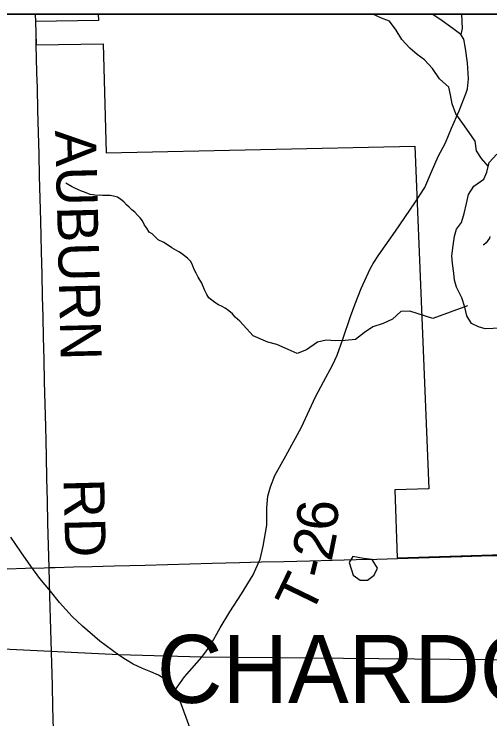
# Model space of a CAD drawing. Extents: x -6.1 to 38, y -7.7 to 22.
# Drawn here: x 4.259 to 4.922, y 19.918 to 20.9 of the extents above; entities that cross this region are included whole.
import ezdxf

# ---------------------------------------------------------------- set-up
doc = ezdxf.new("R2010")
doc.units = 0
for name, color, linetype in [('GM_X_Corporation', 7, 'Continuous'), ('GM_X_Corporation_Text', 7, 'Continuous'), ('GM_X_County_Road', 7, 'Continuous'), ('GM_X_County_Road_Text', 7, 'Continuous'), ('GM_X_Minor_Lake', 7, 'Continuous'), ('GM_X_Minor_River', 7, 'Continuous'), ('GM_X_Township_Road', 7, 'Continuous'), ('GM_X_Township_Road_Text', 7, 'Continuous'), ('GM_X_US_Route', 7, 'Continuous'), ('SH_Data', 7, 'Continuous')]:
    doc.layers.add(name, color=color, linetype=linetype)

msp = doc.modelspace()

# ---------------------------------------------------------------- linework, layer by layer
at = {"layer": 'GM_X_Corporation'}
for points in [[(4.22089, 19.39843), (4.27649, 19.3997), (4.32704, 19.40086), (4.34441, 19.40116), (4.39909, 19.40211), (4.59553, 19.40667), (4.87412, 19.41274), (4.97606, 19.41491), (5.07728, 19.4172), (5.13005, 19.41862), (5.18283, 19.42005), (5.26822, 19.42235), (5.32463, 19.42402), (6.10501, 19.44291), (6.34755, 19.45258), (6.9731, 19.47266), (6.99327, 19.47331), (6.9774, 20.19314), (6.97663, 20.24175), (6.97563, 20.30513), (6.97445, 20.38052), (6.96628, 20.9), (2.1, 20.9)], [(8.04941, 20.9), (3.3101, 20.9)], [(7.14717, 20.9), (4.37651, 20.9), (4.37679, 20.89098), (4.28899, 20.88957), (4.28982, 20.85699), (4.38331, 20.85847), (4.38778, 20.70692), (4.81787, 20.71611), (4.83725, 20.23904), (4.79001, 20.23763), (4.79328, 20.14293), (4.96982, 20.1482), (5.06265, 20.15096), (5.06609, 20.01834), (5.06874, 19.91759), (5.08464, 19.50072), (5.08782, 19.41822), (5.14515, 19.41957), (5.32421, 19.42375), (5.35638, 19.42473), (5.69625, 19.43438)], [(3.57893, 20.04876), (4.40517, 20.00794), (4.52052, 20.00493), (5.06432, 19.99968), (5.10588, 19.99873), (5.44207, 19.98944), (5.85226, 19.97619), (6.03347, 19.96996), (6.05243, 19.96934), (6.44715, 19.95634), (6.50311, 19.95448), (6.5387, 19.95281), (6.57375, 19.95116), (6.60957, 19.94948), (6.64602, 19.94776), (6.72175, 19.94421), (6.77262, 19.94188), (6.8325, 19.93914), (6.8881, 19.93659), (7.17492, 19.92346)], [(3.57893, 20.04876), (4.40517, 20.00794), (4.52052, 20.00493), (5.06432, 19.99968), (5.10588, 19.99873), (5.44207, 19.98944), (5.85226, 19.97619), (6.03347, 19.96996), (6.05243, 19.96934), (6.44715, 19.95634), (6.50311, 19.95448), (6.5387, 19.95281), (6.57375, 19.95116), (6.60957, 19.94948), (6.64602, 19.94776), (6.72175, 19.94421), (6.77262, 19.94188), (6.8325, 19.93914), (6.8881, 19.93659), (7.17492, 19.92346)]]:
    msp.add_lwpolyline(points, dxfattribs=at)
at = {"layer": 'GM_X_County_Road'}
for p, q in [((4.28953, 20.88913), (4.28925, 20.9)), ((4.29026, 20.85635), (4.29006, 20.86537))]:
    msp.add_line(p, q, dxfattribs=at)
for points in [[(4.29006, 20.86537), (4.28988, 20.87339), (4.28953, 20.88913)], [(4.31423, 19.9036), (4.31341, 19.93465), (4.31259, 19.96532), (4.31178, 19.99599), (4.31096, 20.02705), (4.31014, 20.05811), (4.30972, 20.07397), (4.3093, 20.08983), (4.30866, 20.10946), (4.30802, 20.12909), (4.30728, 20.16015), (4.30653, 20.19122), (4.30579, 20.22228), (4.30504, 20.25334), (4.30431, 20.2844), (4.30381, 20.30505), (4.30332, 20.32569), (4.30257, 20.35676), (4.30183, 20.38782), (4.30109, 20.41888), (4.30035, 20.44994), (4.29967, 20.47826), (4.29899, 20.50659), (4.29825, 20.53765), (4.2975, 20.56871), (4.29699, 20.59047), (4.29646, 20.61221), (4.29565, 20.64327), (4.29484, 20.67433), (4.29404, 20.70483), (4.29324, 20.73533), (4.29248, 20.76639), (4.29172, 20.79746), (4.29121, 20.81832), (4.2907, 20.83918), (4.29026, 20.85635)], [(4.40809, 20.00559), (4.40538, 20.0074), (4.37871, 20.02672), (4.35441, 20.04768), (4.34036, 20.0613), (4.3227, 20.08077), (4.30992, 20.09614), (4.29514, 20.11412), (4.28256, 20.13109), (4.26879, 20.15126), (4.25481, 20.17163)], [(4.76276, 19.67326), (4.74622, 19.67808), (4.72547, 19.68499), (4.68964, 19.70008), (4.65465, 19.71454), (4.60479, 19.73653), (4.58907, 19.74554), (4.57168, 19.75916), (4.5589, 19.77425), (4.54968, 19.78934), (4.54235, 19.80505), (4.52894, 19.84067), (4.50296, 19.91002), (4.49227, 19.93957), (4.48787, 19.95025), (4.48347, 19.958), (4.46945, 19.97365), (4.46072, 19.97935), (4.44972, 19.9839), (4.43801, 19.9888), (4.42544, 19.99446), (4.41443, 20.00136), (4.40809, 20.00559)]]:
    msp.add_lwpolyline(points, dxfattribs=at)
at = {"layer": 'GM_X_Minor_Lake'}
for points in [[(4.7461, 20.14187), (4.73133, 20.1445), (4.72607, 20.13613), (4.73182, 20.11868), (4.74169, 20.11149), (4.7519, 20.1119)], [(4.7519, 20.1119), (4.76096, 20.11875), (4.76584, 20.12825), (4.75822, 20.14039), (4.7461, 20.14187)]]:
    msp.add_lwpolyline(points, dxfattribs=at)
at = {"layer": 'GM_X_Minor_River'}
for points in [[(4.91971, 20.68834), (4.91039, 20.69909), (4.90355, 20.70969), (4.90162, 20.72295), (4.89327, 20.73506), (4.88454, 20.74755), (4.87504, 20.76117), (4.86971, 20.77519), (4.86741, 20.78769), (4.86511, 20.79831), (4.85222, 20.80964), (4.84235, 20.8244), (4.83097, 20.83612), (4.82111, 20.84367), (4.81088, 20.85236), (4.7995, 20.86485), (4.7919, 20.87771), (4.78241, 20.8902), (4.77143, 20.89434), (4.75938, 20.9)], [(4.87184, 20.53921), (4.87028, 20.55288), (4.86948, 20.56351), (4.87093, 20.57794), (4.87315, 20.59085), (4.87576, 20.60035), (4.88292, 20.60986), (4.88665, 20.6224), (4.88962, 20.63608), (4.8926, 20.64862), (4.89975, 20.66041), (4.91371, 20.66993), (4.91821, 20.67981), (4.92119, 20.69311), (4.93174, 20.70491)], [(4.5926, 20.45177), (4.57368, 20.47256), (4.56724, 20.47784), (4.56344, 20.48275), (4.55851, 20.4869), (4.5532, 20.49067), (4.54828, 20.4933), (4.54411, 20.49518), (4.53881, 20.49857), (4.53464, 20.50159), (4.53047, 20.50498), (4.5278, 20.50952), (4.52475, 20.51595), (4.52284, 20.52049), (4.52093, 20.52542), (4.51598, 20.53374), (4.51294, 20.53941), (4.51027, 20.54433), (4.50721, 20.5519), (4.50493, 20.55606), (4.50075, 20.56021), (4.49279, 20.56663), (4.48863, 20.56888), (4.47915, 20.57453), (4.47157, 20.57943), (4.46779, 20.58206), (4.45983, 20.58582), (4.45566, 20.5896), (4.45149, 20.59413), (4.4477, 20.59639), (4.44427, 20.60168), (4.44123, 20.60622), (4.43818, 20.61189), (4.43514, 20.61643), (4.43135, 20.61983), (4.42755, 20.62398), (4.42338, 20.62738), (4.41958, 20.63115), (4.41579, 20.63455), (4.412, 20.6387), (4.4082, 20.64172), (4.40328, 20.64511), (4.39798, 20.64661), (4.39307, 20.64735), (4.38853, 20.64733), (4.38249, 20.6473), (4.37833, 20.64766), (4.37417, 20.64727), (4.36926, 20.64839), (4.3651, 20.64874), (4.35753, 20.65213), (4.35337, 20.65325), (4.34882, 20.65512), (4.3439, 20.65776), (4.33936, 20.66001), (4.3314, 20.66453)], [(4.92243, 20.59048), (4.92172, 20.5878), (4.91728, 20.58126), (4.91391, 20.57854), (4.91315, 20.57852)], [(4.96033, 20.46348), (4.91568, 20.46186), (4.9062, 20.46449), (4.89673, 20.46903), (4.89025, 20.48002), (4.88717, 20.49179), (4.88296, 20.50507), (4.87571, 20.51948), (4.87302, 20.52934), (4.87184, 20.53921)], [(4.89119, 20.49357), (4.84292, 20.4759), (4.81074, 20.48642), (4.79826, 20.486), (4.78657, 20.47535), (4.77372, 20.46924), (4.75937, 20.46426), (4.74766, 20.45664), (4.73521, 20.44675), (4.72046, 20.44556), (4.70723, 20.44514), (4.69399, 20.44586), (4.68227, 20.44317), (4.66679, 20.4325), (4.65357, 20.42753), (4.64107, 20.4328), (4.62555, 20.43996), (4.61306, 20.44296), (4.5926, 20.45177)]]:
    msp.add_lwpolyline(points, dxfattribs=at)
at = {"layer": 'GM_X_Township_Road'}
for points in [[(4.88157, 20.87174), (4.87068, 20.87972), (4.85255, 20.89271), (4.84204, 20.9)], [(4.88268, 20.9), (4.88366, 20.88012), (4.88157, 20.87174)], [(4.52722, 20.01313), (4.53313, 20.02107), (4.54633, 20.04537), (4.55995, 20.06737), (4.57608, 20.09273), (4.59222, 20.11892), (4.60206, 20.14091), (4.60625, 20.15914), (4.6117, 20.18806), (4.61149, 20.21258), (4.61275, 20.2285), (4.61673, 20.2417), (4.62281, 20.25741), (4.6379, 20.2848), (4.65989, 20.32488), (4.67938, 20.36678), (4.69027, 20.38795), (4.70305, 20.41099), (4.70943, 20.42515), (4.7173, 20.44724), (4.7282, 20.47867), (4.73448, 20.49648), (4.74307, 20.51785), (4.75543, 20.5453), (4.75956, 20.55283), (4.76737, 20.56478), (4.79084, 20.59768), (4.81766, 20.63707), (4.83149, 20.65844), (4.84071, 20.68023), (4.85035, 20.7016), (4.86062, 20.72067), (4.86858, 20.741), (4.87969, 20.76551), (4.88901, 20.7903), (4.89123, 20.79611), (4.89231, 20.80991), (4.89096, 20.8321), (4.88827, 20.85225), (4.88576, 20.86524), (4.88157, 20.87174)], [(4.48347, 19.958), (4.49679, 19.9769), (4.52073, 20.00439), (4.52722, 20.01313)]]:
    msp.add_lwpolyline(points, dxfattribs=at)
at = {"layer": 'GM_X_US_Route'}
for points in [[(4.24952, 20.12754), (4.27526, 20.12825), (4.30099, 20.12894), (4.30802, 20.12909), (4.3163, 20.12933), (4.34208, 20.13009), (4.36787, 20.13084), (4.39892, 20.13165), (4.42048, 20.13221), (4.44203, 20.13277), (4.47308, 20.13358), (4.50414, 20.13439), (4.53519, 20.13519), (4.5542, 20.13569), (4.5732, 20.13619), (4.60426, 20.137), (4.63532, 20.1378), (4.65335, 20.13828), (4.67138, 20.13874), (4.70244, 20.13947), (4.71911, 20.13986), (4.73577, 20.14025), (4.76469, 20.14105), (4.7936, 20.14184)], [(4.7936, 20.14184), (4.8232, 20.14286), (4.85279, 20.14387), (4.88385, 20.14467), (4.91058, 20.14535), (4.9373, 20.14604), (4.95392, 20.14652), (4.97055, 20.14701), (4.99345, 20.1477), (5.01635, 20.14839), (5.03954, 20.14911), (5.06273, 20.14984)]]:
    msp.add_lwpolyline(points, dxfattribs=at)
at = {"layer": 'SH_Data'}
msp.add_line((2.1, 20.9), (8.9, 20.9), dxfattribs=at)

# ---------------------------------------------------------------- texts
at = {"layer": 'GM_X_Corporation_Text'}
msp.add_text('CHARDON', height=0.094697, rotation=0.00001, dxfattribs=at).set_placement((4.45819, 19.94075))
at = {"layer": 'GM_X_County_Road_Text'}
for s, rotation, p in [('AUBURN', 271.46401, (4.31639, 20.73778)), ('RD', 271.46992, (4.32805, 20.25255))]:
    msp.add_text(s, height=0.056818, rotation=rotation, dxfattribs=at).set_placement(p)
at = {"layer": 'GM_X_Township_Road_Text'}
for s, rotation, p in [('6', 87.24261, (4.70954, 20.17985)), ('2', 78.59972, (4.70147, 20.13628)), ('-', 76.33931, (4.69542, 20.11121)), ('T', 64.20351, (4.67251, 20.06062))]:
    msp.add_text(s, height=0.05682, rotation=rotation, dxfattribs=at).set_placement(p)

doc.saveas('drawing.dxf')
